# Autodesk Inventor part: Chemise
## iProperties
Shininess: 64.0
Length Units: 11269
Angle Units: 11279
Time Units: 11290
Mass Units: 11283
Length Display Precision: 3
Angle Display Precision: 2
Compacted: True
Part Number: Chemise
Document SubType Name: Modeling
Created: 2005-01
Material: Par défaut
Designer: Flavien MARTY
Density: 0.0
Volumn: 0.0
Area: 0.0
PropertySet Name: Model Information
Control State: 0
Master: False
Checked Out: False
Norme de conversion: STEP AP203
Nom du fichier: Chemise.STEP
Préprocesseur: SolidWorks 2001039
Postprocesseur: Build: Release: 6 RTM Build: 90b - Date: Tue 09/24/2002
Unités envoyées: MILLIMETERS
Incertitude: 0.0
Author: Flavien MARTY
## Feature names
1. Base1
